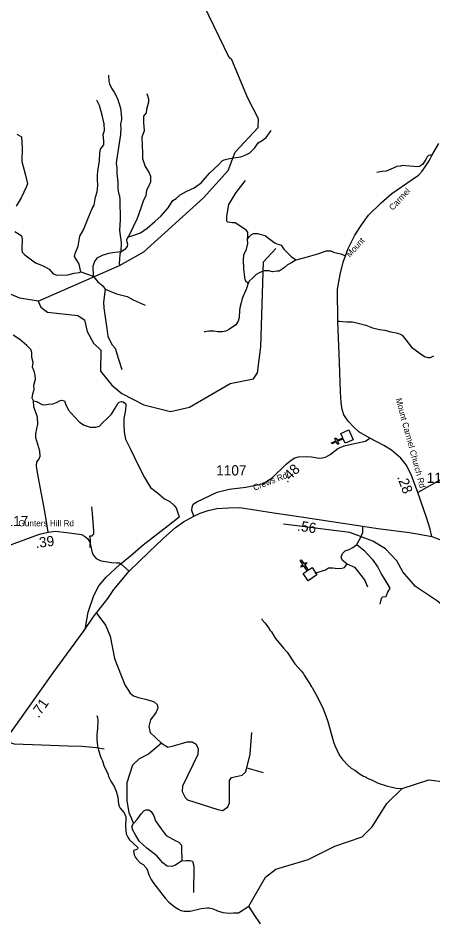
# Model space of a CAD drawing. Extents: x 1248224 to 1454986, y 825081 to 985870.
# Drawn here: x 1338152 to 1343240, y 854081 to 865144 of the extents above; entities that cross this region are included whole.
import ezdxf

# ---------------------------------------------------------------- set-up
doc = ezdxf.new("R2010")
doc.units = 0
for name, color, linetype in [('Exist Cultural Church CELL', 7, 'Continuous'), ('Exist Hydrographic Creek Single Shore', 7, 'Continuous'), ('Exist Hydrographic Misc Water Feature', 7, 'Continuous'), ('Exist Road Non-System Type 51', 7, 'Continuous'), ('Exist Road Primary NC Attributed', 7, 'Continuous'), ('Exist Road Primary NC Mileage Hundredths English Label', 7, 'Continuous'), ('Exist Road Secondary Mileage Hundredths English Label', 7, 'Continuous'), ('Exist Road Secondary Type 51 Attributed', 7, 'Continuous'), ('Exist Road Secondary Type 51 Label', 7, 'Continuous'), ('Exist Road Secondary Type 51 Number Label', 7, 'Continuous')]:
    doc.layers.add(name, color=color, linetype=linetype)

msp = doc.modelspace()

# ---------------------------------------------------------------- linework, layer by layer
at = {"layer": 'Exist Cultural Church CELL'}
for points in [[(1342164, 859935), (1342141, 859987), (1342071, 859957), (1342084, 859927), (1342069, 859921), (1342057, 859950), (1342001, 859926), (1341995, 859941), (1342050, 859965), (1342037, 859994), (1342052, 860001), (1342065, 859971), (1342135, 860002), (1342112, 860055), (1342209, 860097), (1342262, 859977)], [(1341650, 858339), (1341697, 858370), (1341655, 858434), (1341629, 858416), (1341620, 858429), (1341646, 858447), (1341613, 858497), (1341626, 858506), (1341660, 858456), (1341686, 858474), (1341695, 858460), (1341669, 858443), (1341711, 858379), (1341759, 858411), (1341818, 858323), (1341709, 858250)]]:
    msp.add_lwpolyline(points, close=True, dxfattribs=at)
at = {"layer": 'Exist Hydrographic Creek Single Shore'}
msp.add_lwpolyline([(1341125, 854046), (1341049, 854158), (1340984, 854262), (1341031, 854346), (1341187, 854619), (1341314, 854715), (1341708, 854832), (1342037, 854999), (1342373, 855110), (1342493, 855233), (1342674, 855521), (1342861, 855704), (1343189, 855810), (1343380, 855786)], dxfattribs=at)
at = {"layer": 'Exist Hydrographic Misc Water Feature'}
for points in [[(1338399, 861677), (1339397, 862114), (1339696, 862281), (1340428, 862940), (1340727, 863275), (1340815, 863500), (1341097, 863803), (1341099, 863911), (1340972, 864163), (1340773, 864633), (1340741, 864660), (1340374, 865426)], [(1339260, 864445), (1339264, 864373), (1339272, 864340), (1339298, 864284), (1339333, 864235), (1339370, 864158), (1339407, 864041), (1339414, 864005), (1339414, 863991), (1339418, 863985), (1339420, 863901), (1339410, 863845), (1339410, 863821), (1339414, 863805), (1339410, 863717), (1339358, 863399), (1339357, 863361), (1339362, 863310), (1339363, 863239), (1339374, 863134), (1339377, 863054), (1339383, 863000), (1339395, 862966), (1339399, 862918), (1339406, 862673), (1339397, 862546), (1339403, 862478), (1339413, 862433), (1339417, 862385), (1339411, 862289), (1339402, 862250), (1339395, 862186), (1339394, 862140), (1339397, 862114)], [(1338399, 861677), (1338174, 861714), (1337610, 861948), (1337224, 862101), (1336911, 862285), (1336704, 862348), (1336462, 862327), (1336210, 862250), (1336041, 862145), (1335974, 862146), (1335917, 862196), (1335792, 862609), (1335543, 863015), (1335502, 863042), (1335386, 863028)], [(1338399, 861677), (1338430, 861601), (1338512, 861540), (1338887, 861500), (1338969, 861446), (1338999, 861304), (1339079, 861161), (1339169, 861074), (1339163, 860818), (1339301, 860648), (1339424, 860544), (1339696, 860404), (1340020, 860322), (1340255, 860376), (1340753, 860665), (1341038, 860725), (1341089, 860799), (1341130, 861117), (1341161, 862157), (1341315, 862321)], [(1345844, 854850), (1345727, 855194), (1345671, 855313), (1345336, 855629), (1345143, 855908), (1345055, 856110), (1344998, 856561), (1344926, 856681), (1344459, 857032), (1343296, 858000), (1343024, 858180), (1342870, 858360), (1342798, 858493), (1342659, 858640), (1342503, 858735), (1342222, 858839), (1341407, 858941)], [(1341142, 857781), (1341143, 857773), (1341180, 857732), (1341233, 857663), (1341240, 857646), (1341260, 857622), (1341287, 857573), (1341310, 857541), (1341407, 857423), (1341454, 857373), (1341547, 857231), (1341629, 857141), (1341652, 857109), (1341660, 857093), (1341679, 857068), (1341704, 857022), (1341722, 856999), (1341749, 856950), (1341757, 856942), (1341830, 856813), (1341893, 856679), (1341927, 856594), (1341949, 856526), (1342020, 856274), (1342037, 856232), (1342094, 856110), (1342129, 856058), (1342195, 855988), (1342238, 855955), (1342284, 855928), (1342349, 855880), (1342388, 855855), (1342422, 855841), (1342432, 855832), (1342485, 855811), (1342570, 855771), (1342670, 855735), (1342789, 855708), (1342861, 855704)], [(1339120, 856597), (1339126, 856573), (1339129, 856533), (1339127, 856445), (1339124, 856397), (1339119, 856375), (1339118, 856309), (1339128, 856221), (1339139, 856173), (1339169, 856084), (1339188, 856044), (1339206, 855987), (1339256, 855874), (1339263, 855850), (1339290, 855793), (1339329, 855728), (1339355, 855672), (1339376, 855599), (1339384, 855511), (1339391, 855487), (1339403, 855463), (1339453, 855405), (1339474, 855357), (1339476, 855341), (1339471, 855237), (1339479, 855149), (1339497, 855108), (1339518, 855076), (1339623, 854981), (1339622, 854972), (1339617, 854965), (1339609, 854958), (1339595, 854952), (1339579, 854948), (1339571, 854943), (1339567, 854935), (1339578, 854890), (1339593, 854858), (1339605, 854842), (1339651, 854795), (1339687, 854772), (1339724, 854733), (1339739, 854703), (1339756, 854646), (1339783, 854590), (1339806, 854557), (1339958, 854361), (1340003, 854312), (1340079, 854251), (1340119, 854226), (1340150, 854211), (1340190, 854200), (1340230, 854199), (1340262, 854202), (1340399, 854233), (1340471, 854243), (1340479, 854241), (1340495, 854243), (1340543, 854230), (1340598, 854204), (1340662, 854185), (1340742, 854177), (1340796, 854182), (1340854, 854182), (1340984, 854262)]]:
    msp.add_lwpolyline(points, dxfattribs=at)
at = {"layer": 'Exist Road Non-System Type 51'}
msp.add_line((1340958, 855957), (1341157, 855902), dxfattribs=at)
for points in [[(1339732, 864220), (1339751, 864155), (1339751, 864115), (1339729, 864023), (1339723, 863983), (1339689, 863943), (1339692, 863866), (1339698, 863761), (1339671, 863687), (1339674, 863588), (1339680, 863490), (1339680, 863422), (1339711, 863327), (1339757, 863256), (1339775, 863208), (1339775, 863137), (1339763, 863106), (1339729, 863035), (1339720, 862968), (1339692, 862915), (1339661, 862829), (1339615, 862687), (1339514, 862485), (1339498, 862461)], [(1338924, 862033), (1338902, 862129), (1338846, 862222), (1338852, 862259), (1338889, 862348), (1338908, 862471), (1338957, 862551), (1338997, 862653), (1339019, 862711), (1339061, 862811), (1339086, 862851), (1339101, 862949), (1339123, 863017), (1339129, 863091), (1339126, 863168), (1339126, 863217), (1339132, 863267), (1339151, 863393), (1339154, 863491), (1339163, 863538), (1339203, 863593), (1339206, 863642), (1339197, 863719), (1339212, 863766), (1339209, 863849), (1339182, 863953), (1339151, 864075), (1339120, 864137)], [(1338138, 863722), (1338193, 863691), (1338202, 863553), (1338199, 863386), (1338245, 863220), (1338267, 863115), (1338258, 863081), (1338190, 862943), (1338131, 862841)], [(1339498, 862461), (1339572, 862485), (1339652, 862513), (1339735, 862569), (1339828, 862652), (1339908, 862723), (1339994, 862818), (1340052, 862907), (1340092, 862932), (1340141, 862978), (1340215, 863020), (1340313, 863066), (1340399, 863125), (1340501, 863245), (1340609, 863346), (1340655, 863393), (1340679, 863408), (1340729, 863420), (1340796, 863430), (1340883, 863442), (1340947, 863470), (1340993, 863494), (1341055, 863556), (1341098, 863614), (1341144, 863645), (1341196, 863682), (1341255, 863765)], [(1343228, 863459), (1343213, 863463), (1343206, 863463), (1343186, 863461), (1343171, 863446), (1343153, 863411), (1343111, 863351), (1343074, 863324), (1343047, 863322), (1343004, 863326), (1342956, 863330), (1342907, 863335), (1342867, 863337), (1342843, 863330), (1342797, 863324), (1342754, 863306), (1342696, 863279), (1342665, 863270), (1342617, 863264), (1342553, 863252)], [(1340975, 861895), (1340955, 861907), (1340938, 861936), (1340924, 862035), (1340920, 862073), (1340916, 862180), (1340920, 862244), (1340955, 862311), (1340971, 862381), (1340967, 862435), (1340969, 862466), (1340971, 862519), (1340951, 862544), (1340849, 862615), (1340815, 862634), (1340784, 862634), (1340726, 862643), (1340714, 862657), (1340714, 862717), (1340737, 862860), (1340827, 863007), (1340941, 863156)], [(1338115, 862528), (1338167, 862498), (1338195, 862476), (1338204, 862436), (1338198, 862313), (1338201, 862276), (1338235, 862242), (1338367, 862146), (1338460, 862110), (1338534, 862066), (1338583, 862011), (1338626, 861992), (1338761, 861999), (1338841, 862017), (1338903, 862026), (1338924, 862033)], [(1340967, 862435), (1340986, 862465), (1341001, 862482), (1341017, 862494), (1341040, 862505), (1341090, 862505), (1341116, 862497), (1341183, 862482), (1341228, 862443), (1341300, 862391), (1341327, 862379), (1341354, 862370), (1341377, 862362), (1341412, 862314), (1341458, 862269), (1341501, 862223), (1341528, 862203), (1341564, 862182)], [(1339498, 862461), (1339483, 862424), (1339486, 862403), (1339495, 862372), (1339489, 862347), (1339462, 862307), (1339415, 862280), (1339342, 862271), (1339261, 862261), (1339185, 862237), (1339117, 862203), (1339089, 862163), (1339068, 862101), (1339074, 861981)], [(1341564, 862182), (1341686, 862213), (1341827, 862255), (1341911, 862284), (1341934, 862292), (1341986, 862292), (1342021, 862277), (1342052, 862267), (1342110, 862257), (1342168, 862232)], [(1341564, 862182), (1341496, 862143), (1341455, 862122), (1341416, 862083), (1341354, 862044), (1341325, 862042), (1341271, 862035), (1341228, 862048), (1341170, 862048), (1341116, 862025), (1341071, 862002), (1341027, 861959), (1340992, 861926), (1340975, 861895)], [(1338924, 862033), (1339003, 862006), (1339074, 861981), (1339132, 861914), (1339191, 861864), (1339222, 861821)], [(1340975, 861895), (1340955, 861829), (1340902, 861709), (1340889, 861655), (1340873, 861595), (1340866, 861556), (1340864, 861475), (1340850, 861432), (1340821, 861386), (1340745, 861331), (1340701, 861306), (1340660, 861298), (1340598, 861300), (1340552, 861306), (1340530, 861309), (1340492, 861306), (1340443, 861300), (1340432, 861296)], [(1339222, 861821), (1339200, 861664), (1339206, 861593), (1339228, 861424), (1339243, 861340), (1339255, 861241), (1339305, 861142), (1339345, 861099), (1339385, 860963), (1339425, 860837)], [(1339222, 861821), (1339360, 861764), (1339492, 861733), (1339566, 861690), (1339711, 861625)], [(1342074, 861431), (1342095, 861431), (1342136, 861426), (1342184, 861422), (1342248, 861424), (1342289, 861414), (1342415, 861381), (1342498, 861350), (1342583, 861327), (1342649, 861321), (1342723, 861300), (1342810, 861282), (1342845, 861269), (1342864, 861257), (1342936, 861166), (1342978, 861110), (1343083, 861035), (1343135, 860998), (1343176, 860986), (1343211, 860986), (1343251, 861007)], [(1338342, 860456), (1338327, 860487), (1338333, 860540), (1338351, 860592), (1338345, 860644), (1338367, 860721), (1338364, 860767), (1338348, 860817), (1338330, 860866), (1338336, 860924), (1338320, 860986), (1338320, 861045), (1338308, 861085), (1338262, 861134), (1338176, 861205), (1338093, 861257)], [(1338342, 860456), (1338379, 860447), (1338449, 860410), (1338477, 860407), (1338526, 860413), (1338579, 860416), (1338622, 860435), (1338659, 860453), (1338690, 860463), (1338723, 860456), (1338736, 860416), (1338770, 860339), (1338843, 860259), (1338905, 860192), (1338963, 860155), (1339037, 860130), (1339105, 860130), (1339151, 860145), (1339185, 860179), (1339253, 860244), (1339299, 860290), (1339345, 860364), (1339376, 860420), (1339394, 860438), (1339419, 860444), (1339440, 860441), (1339471, 860420), (1339474, 860401), (1339468, 860343), (1339450, 860235), (1339450, 860155), (1339453, 860075), (1339471, 859985), (1339530, 859862), (1339631, 859659), (1339704, 859516), (1339778, 859392), (1339861, 859325), (1339950, 859254), (1340015, 859220), (1340064, 859177), (1340092, 859143), (1340127, 859034)], [(1338483, 859075), (1338458, 859229), (1338397, 859550), (1338378, 859654), (1338381, 859707), (1338409, 859734), (1338424, 859777), (1338418, 859836), (1338369, 860002), (1338370, 860053), (1338397, 860167), (1338391, 860256), (1338345, 860382), (1338342, 860456)], [(1343398, 859521), (1343192, 859410), (1343055, 859332)], [(1338522, 858844), (1338483, 859075)], [(1339037, 858656), (1339040, 858749), (1339034, 858799), (1339061, 858802), (1339080, 858823), (1339080, 858860), (1339064, 859073), (1339058, 859156)], [(1339402, 858447), (1339531, 858554), (1339687, 858691), (1339994, 858928), (1340127, 859034)], [(1342306, 858692), (1342356, 858783), (1342379, 858839), (1342382, 858879), (1342379, 858918)], [(1342185, 858458), (1342129, 858499), (1342115, 858539), (1342132, 858582), (1342162, 858615), (1342212, 858632), (1342259, 858659), (1342306, 858692)], [(1342306, 858692), (1342392, 858626), (1342496, 858515), (1342563, 858418), (1342603, 858335), (1342676, 858221), (1342710, 858158), (1342683, 858111), (1342663, 858051), (1342623, 858047), (1342606, 858034), (1342589, 857964)], [(1338980, 857676), (1339014, 857863), (1339080, 858070), (1339144, 858186), (1339234, 858293), (1339402, 858447)], [(1341795, 858342), (1341922, 858385), (1341958, 858408), (1342012, 858408), (1342068, 858398), (1342122, 858402), (1342155, 858412), (1342169, 858428), (1342185, 858458)], [(1342185, 858458), (1342276, 858418), (1342312, 858375), (1342399, 858261), (1342436, 858174)], [(1339120, 857849), (1339224, 857706), (1339284, 857572), (1339334, 857298), (1339461, 856976), (1339529, 856871), (1339569, 856839), (1339630, 856817), (1339733, 856795), (1339821, 856765), (1339860, 856733), (1339868, 856687), (1339848, 856638), (1339777, 856547), (1339755, 856464), (1339773, 856391), (1339910, 856258)], [(1340958, 855957), (1340997, 856125), (1341020, 856391)], [(1337996, 856304), (1338077, 856260), (1338106, 856250), (1338441, 856237), (1338764, 856227), (1338935, 856222), (1339115, 856206), (1339207, 856189)], [(1339910, 856258), (1339754, 856125), (1339637, 856066), (1339555, 855988), (1339488, 855775), (1339485, 855554), (1339510, 855409), (1339569, 855277)], [(1339910, 856258), (1339988, 856211), (1340059, 856227), (1340227, 856274), (1340289, 856274), (1340336, 856246), (1340360, 856188), (1340356, 856121), (1340168, 855734), (1340164, 855667), (1340200, 855593), (1340230, 855564), (1340602, 855448), (1340665, 855433), (1340723, 855480), (1340747, 855530), (1340747, 855640), (1340747, 855800), (1340770, 855840), (1340829, 855851), (1340899, 855867), (1340942, 855906), (1340958, 855957)], [(1339569, 855277), (1339613, 855326), (1339664, 855392), (1339694, 855431), (1339721, 855444), (1339757, 855444), (1339784, 855424), (1339816, 855370), (1339838, 855306), (1339907, 855208), (1339970, 855130), (1340088, 855064), (1340122, 855046), (1340157, 855010), (1340157, 854968), (1340162, 854816), (1340162, 854816)], [(1340162, 854816), (1340083, 854764), (1340039, 854747), (1339980, 854752), (1339929, 854794), (1339855, 854877), (1339730, 854973), (1339642, 855054), (1339596, 855130), (1339561, 855193), (1339547, 855238), (1339569, 855277)], [(1340162, 854816), (1340213, 854821), (1340260, 854823), (1340291, 854813), (1340306, 854752), (1340304, 854428)]]:
    msp.add_lwpolyline(points, dxfattribs=at)
at = {"layer": 'Exist Road Primary NC Attributed'}
for points in [[(1340307, 859041), (1340385, 859078), (1340482, 859109), (1340591, 859133), (1340735, 859145), (1340874, 859146), (1341287, 859081), (1341626, 859031), (1342000, 858974), (1342379, 858918), (1342566, 858889), (1342952, 858840), (1343115, 858811), (1343226, 858792)], [(1339513, 858365), (1339755, 858601), (1339930, 858769), (1340084, 858901), (1340183, 858972), (1340307, 859041)], [(1343226, 858792), (1343312, 858758), (1343396, 858722), (1343510, 858666), (1343699, 858561), (1343952, 858433), (1344113, 858352), (1344380, 858210), (1344689, 858051), (1344842, 857974), (1345181, 857816), (1345518, 857661), (1345712, 857587), (1345878, 857527), (1345995, 857492), (1346095, 857478), (1346181, 857475), (1346258, 857475), (1346367, 857487), (1346493, 857510), (1347001, 857667)], [(1337610, 855145), (1337717, 855736), (1337734, 855822), (1337760, 855909), (1337781, 855952), (1337805, 856006), (1337866, 856120), (1338105, 856448), (1338582, 857121), (1338962, 857639), (1339074, 857804), (1339252, 858034), (1339326, 858142), (1339513, 858365)]]:
    msp.add_lwpolyline(points, dxfattribs=at)
at = {"layer": 'Exist Road Secondary Type 51 Attributed'}
for points in [[(1342468, 859998), (1342332, 860075), (1342270, 860131), (1342201, 860205), (1342147, 860282), (1342128, 860346), (1342113, 860435), (1342107, 860566), (1342095, 860925), (1342074, 861431), (1342071, 861822), (1342102, 862003), (1342140, 862153), (1342168, 862232), (1342199, 862319), (1342283, 862484), (1342367, 862614), (1342449, 862729), (1342603, 862882), (1342734, 862995), (1342985, 863165), (1343063, 863218), (1343107, 863270), (1343152, 863334), (1343194, 863395), (1343228, 863459), (1343314, 863606)], [(1340307, 859041), (1340283, 859109), (1340287, 859150), (1340299, 859190), (1340344, 859218), (1340595, 859336), (1340740, 859372), (1340944, 859398), (1341090, 859425), (1341160, 859443), (1341269, 859511), (1341442, 859678), (1341501, 859728), (1341546, 859754), (1341590, 859766), (1341690, 859771), (1341751, 859767), (1341844, 859752), (1341882, 859756), (1341921, 859763), (1341978, 859797), (1342074, 859869), (1342152, 859903), (1342295, 859936), (1342411, 859960), (1342441, 859981), (1342468, 859998)], [(1343226, 858792), (1343206, 858880), (1343162, 859023), (1343055, 859332), (1342974, 859551), (1342910, 859671), (1342846, 859750), (1342733, 859848), (1342637, 859905), (1342468, 859998)], [(1337583, 858564), (1337678, 858564), (1337805, 858593), (1338029, 858678), (1338305, 858779), (1338417, 858821), (1338522, 858844), (1338609, 858856), (1338751, 858840), (1338929, 858816), (1338969, 858797), (1339009, 858762), (1339033, 858721), (1339062, 858592), (1339083, 858554), (1339111, 858521), (1339144, 858504), (1339173, 858492), (1339298, 858475), (1339360, 858471), (1339397, 858469), (1339407, 858463), (1339513, 858365)]]:
    msp.add_lwpolyline(points, dxfattribs=at)

# ---------------------------------------------------------------- texts
at = {"layer": 'Exist Road Primary NC Mileage Hundredths English Label'}
for s, rotation, p in [('.56', 351.3588, (1341570, 858865)), ('.71', 55.2052, (1338404, 856561))]:
    msp.add_text(s, height=125, rotation=rotation, dxfattribs=at).set_placement(p)
at = {"layer": 'Exist Road Secondary Mileage Hundredths English Label'}
for s, rotation, p in [('.48', 44.0909, (1341452, 859442)), ('.28', 290.338, (1342799, 859521)), ('.39', 7.6006, (1338373, 858649))]:
    msp.add_text(s, height=125, rotation=rotation, dxfattribs=at).set_placement(p)
at = {"layer": 'Exist Road Secondary Type 51 Label'}
for s, rotation, p in [('Mount                  Carmel', 47.399, (1342220, 862207)), ('Mount Carmel Church Rd', 285.1872, (1342782, 860476)), ('Crews Rd', 21.365, (1341052, 859352))]:
    msp.add_text(s, height=75, rotation=rotation, dxfattribs=at).set_placement(p)
msp.add_text('Gunters Hill Rd', height=75, dxfattribs=at).set_placement((1338158, 858917))
at = {"layer": 'Exist Road Secondary Type 51 Number Label'}
for s, p in [('1107', (1340582, 859540)), ('1106', (1343163, 859449)), ('1117', (1337906, 858919))]:
    msp.add_text(s, height=125, dxfattribs=at).set_placement(p)

doc.saveas('drawing.dxf')
